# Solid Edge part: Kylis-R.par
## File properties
Title: Kylis/R
Author: DESYS
Comments: .
Template: Intrapresa.par
Last saved by: s.pallini
Revision: 40
Application: Solid Edge
Tipo di contenuto documento: 0
Accuracy: 0,990
Descr rev0: Prima emissione
Descr rev1: .
Descr rev2: .
Document Number: 8046/R
Revision: 0
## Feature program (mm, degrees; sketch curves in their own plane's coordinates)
lofted protrusion "unnamed LoftedProtrusion 1"
thinwall "Thinwall_8"  Thickness = 10 mm
fillet "Rotondo_33" radius 4
fillet "Rotondo_34" radius 20
sketch for "ExtrudedProtrusion_7" plane through (-132, 0, 0) normal (1, 0, 0) x-axis (0, -1, 0)
extrude "ExtrudedProtrusion_7" add through along +normal  Profile_Plane1_Distance = 132 mm
sketch for "ExtrudedProtrusion_11" plane through (0, 0, 0) normal (1, 0, 0) x-axis (0, 1, 0)
extrude "ExtrudedProtrusion_11" add finite 140 along -normal
fillet "Rotondo_35" radius 5
sketch for "unnamed Hole 1" plane through (0, 0, 0) normal (1, 0, 0) x-axis (0, 1, 0)
hole "unnamed Hole 1" through
sketch for "ExtrudedCutout_9" plane through (-132, -1, 0) normal (-1, 0, 0) x-axis (0, -1, 0)
extrude "ExtrudedCutout_9" cut finite 8 along -normal
fillet "unnamed Round 1"
fillet "Rotondo_38" radius 3
fillet "Rotondo_41" radius 20
sketch for "unnamed Cutout 1" plane through (-80, -0.0671, -224) normal (0, 0, -1) x-axis (0, 1, 0)
extrude "unnamed Cutout 1" cut to key point along -normal
sketch for "unnamed Cutout 2" plane through (-66.1886, -231.5202, -87.6138) normal (0, 0, 1) x-axis (1, 0, 0)
extrude "unnamed Cutout 2" cut through along -normal
sketch for "ExtrudedCutout_12" plane through (-132, 1, -61.7464) normal (-1, 0, 0) x-axis (0, -1, 0)
  line (-161.5, -142.2536) -> (-161.5, -32.2536)
  line (-161.5, -32.2536) -> (163.5, -32.2536)
  line (163.5, -32.2536) -> (163.5, -142.2536)
  line (-161.5, -142.2536) -> (163.5, -142.2536)
  dimension (linear) = 161.5
  dimension (linear) = 161.5
extrude "ExtrudedCutout_12" cut finite 120 along -normal
sketch for "ExtrudedProtrusion_12" #1 plane through (-154, 1, -9.2464) normal (-1, 0, 0) x-axis (0, -1, 0)
  circle centre (1, 9.2464) radius 35
sketch for "ExtrudedProtrusion_12" #2 plane through (-154, 1, -9.2464) normal (-1, 0, 0) x-axis (0, -1, 0)
  circle centre (1, 9.2464) radius 25
extrude "ExtrudedProtrusion_12" add through along -normal  Profile_Plane1_Distance = 30 mm
draft "Draft_1"  Angles1 = 5 deg
sketch for "ExtrudedProtrusion_13" plane through (0, 0, 0) normal (0, -1, 0) x-axis (1, 0, 0)
extrude "ExtrudedProtrusion_13" add finite 50 symmetric
fillet "Rotondo_42" radius 5
fillet "Rotondo_43" radius 5
fillet "Rotondo_44" radius 5
fillet "Rotondo_45" radius 5
sketch for "Foro_2" plane through (0, -0.0685, 1.452) normal (1, 0, 0) x-axis (0, -1, 0)
hole "Foro_2" diameter 35 through
fillet "Rotondo_46" radius 5
sketch for "ExtrudedCutout_13" plane through (-80, -0.0685, -224) normal (0, 0, -1) x-axis (0, 1, 0)
  line (100.0685, 10) -> (90.0685, 10)
  arc centre (90.0685, 20) radius 10 from (90.0685, 30) to (90.0685, 10) ccw
  line (90.0685, 30) -> (100.0685, 30)
  arc centre (100.0685, 20) radius 10 from (100.0685, 10) to (100.0685, 30) ccw
extrude "ExtrudedCutout_13" cut finite 25 along -normal
sketch for "unnamed Cutout 3" #1 plane through (-80, -0.0685, -224) normal (0, 0, -1) x-axis (0, 1, 0)
  hole centre (-0.0685, 160.452) bore radius 17.5
sketch for "unnamed Cutout 3" #2 plane through (-80, -0.0685, -224) normal (0, 0, -1) x-axis (0, 1, 0)
extrude "unnamed Cutout 3" cut through along -normal
fillet "unnamed Round 2"
fillet "Rotondo_48" radius 10
fillet "Rotondo_50" radius 10
fillet "Rotondo_51" radius 5
fillet "Rotondo_49" radius 2
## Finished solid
Body 1: solid body, 143 faces, 373 edges, 228 vertices.
  Faces by surface: blend 44, cylinder 44, plane 35, sphere 8, offset 4, spline 3, torus 3, swept 2
  Edges by curve: line 130, circle 103, intersection 93, ellipse 28, spline 11, curve on surface 8
Bounding box of the edges (mm; curved faces can reach further): 154.006 x 628.000 x 448.000, from (-154, -314, -224) to (0.0059, 314, 224).
Cylindrical faces by radius (mm): R5 x28, R5.0049 x1, R5.0074 x2, R10 x5, R17.5 x1, R25 x1, R30 x2, R35 x2, R2100 x2
Toroidal faces (ring radius, tube radius in mm): R30 r5 x2, R40 r5 x1
Spherical faces by radius (mm): R5 x8
Planar faces by outward normal: +x 3, +y 3, +z 5, -x 9, -y 3, -z 4, oblique 8
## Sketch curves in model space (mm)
arc centre (99.854, 0, 16.8064) radius 230 from (-130, 0, 25) through (-92.7001, 0, 142.5956) to (0, 0, 224)
arc centre (99.854, 0, -16.8064) radius 230 from (-130, 0, -25) through (-92.7001, 0, -142.5956) to (0, 0, -224)
arc centre (319.3172, 41.2414, -27.8797) radius 450 from (0, 303.9252, -205.4571) through (-101.2967, 173.7534, -117.4594) to (-130, 20.7115, -14.0012)
arc centre (319.3172, -41.2414, 27.8797) radius 450 from (0, -303.9252, 205.4571) through (-101.2967, -173.7534, 117.4594) to (-130, -20.7115, 14.0012)
arc centre (319.3172, -41.2414, -27.8797) radius 450 from (0, -303.9252, -205.4571) through (-101.2967, -173.7534, -117.4594) to (-130, -20.7115, -14.0012)
arc centre (319.3172, 41.2414, 27.8797) radius 450 from (0, 303.9252, 205.4571) through (-101.2967, 173.7534, 117.4594) to (-130, 20.7115, 14.0012)
arc centre (209.3451, -46.0922, 0) radius 340 from (-130, -25, 0) through (-100.7282, -185.5715, 0) to (0, -314, 0)
arc centre (209.3451, 46.0922, 0) radius 340 from (-130, 25, 0) through (-100.7282, 185.5715, 0) to (0, 314, 0)
circle centre (-130, 0, 0) radius 25
arc centre (0, 0, 2276) radius 2500 from (0, -303.9252, -205.4571) through (0, 0, -224) to (0, 303.9252, -205.4571)
arc centre (0, -1786, 0) radius 2100 from (0, 303.9252, 205.4571) through (0, 314, 0) to (0, 303.9252, -205.4571)
arc centre (0, 0, -2276) radius 2500 from (0, -303.9252, 205.4571) through (0, 0, 224) to (0, 303.9252, 205.4571)
arc centre (0, 1786, 0) radius 2100 from (0, -303.9252, 205.4571) through (0, -314, 0) to (0, -303.9252, -205.4571)
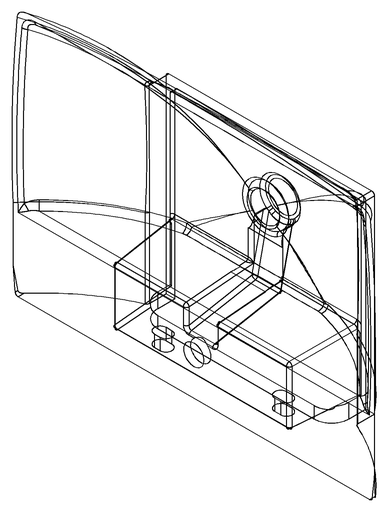
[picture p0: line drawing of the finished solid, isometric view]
